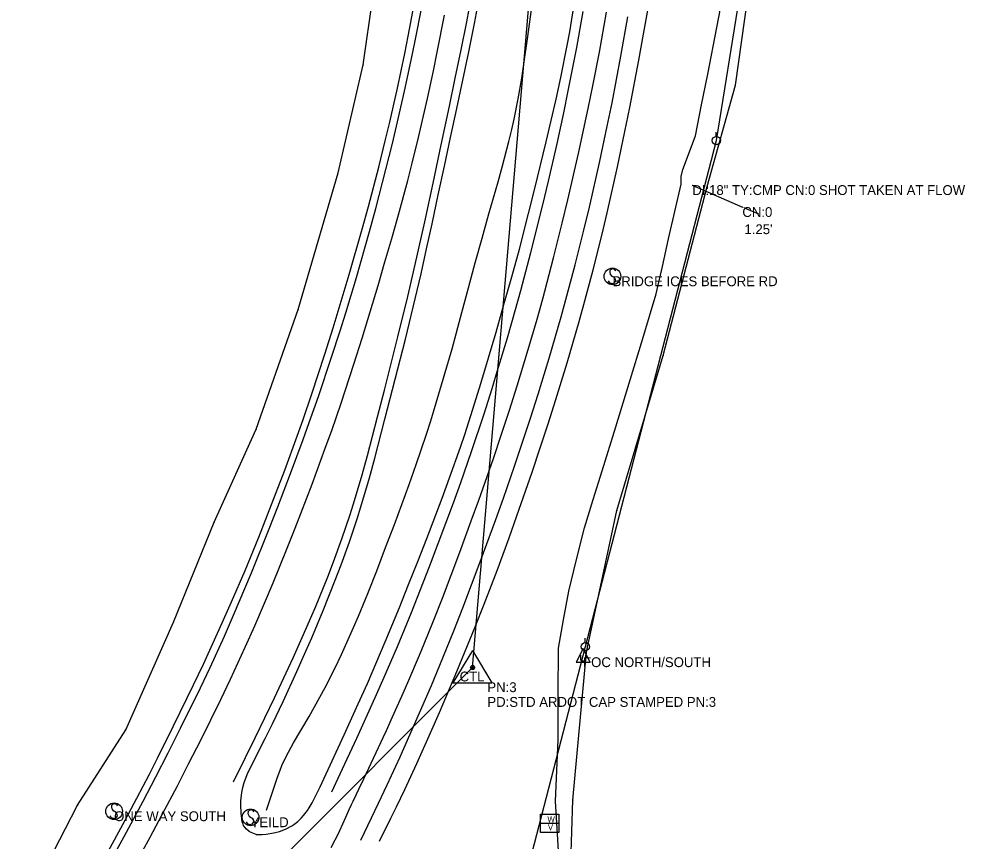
# Model space of a CAD drawing. Extents: x 1676038 to 1677961, y 226475 to 233854.
# Drawn here: x 1677137.5 to 1677618.5, y 228300.9 to 228719 of the extents above; entities that cross this region are included whole.
import ezdxf

# ---------------------------------------------------------------- set-up
doc = ezdxf.new("R2010")
doc.units = 0
for name, color, linetype in [('S_BASELINE', 7, 'Continuous'), ('S_CROSS_DRAIN', 7, 'Continuous'), ('S_CROSS_DRAIN_ANNOT', 7, 'Continuous'), ('S_DITCHLINE', 7, 'Continuous'), ('S_DRG_PT_SYM', 7, 'Continuous'), ('S_DROP_INLET_ANNOT', 7, 'Continuous'), ('S_EDGE_PAVEMENT', 7, 'Continuous'), ('S_ELECTRIC_UTILITIES', 7, 'Continuous'), ('S_FIBER_OPTIC_CABLE', 7, 'Continuous'), ('S_MSC_PT_SYM', 7, 'Continuous'), ('S_PAVEMENT_CROWN', 7, 'Continuous'), ('S_PRIMARY_CTL', 7, 'Continuous'), ('S_PRIMARY_CTL_ANNOT', 7, 'Continuous'), ('S_SHOULDER', 7, 'Continuous'), ('S_SIGN', 7, 'Continuous'), ('S_SIGN_ANNOT', 7, 'Continuous'), ('S_UNDERGROUND_CABLE', 7, 'Continuous'), ('S_UTILITY_POLE', 7, 'Continuous'), ('S_UTILITY_POLE_ANNOT', 7, 'Continuous'), ('S_UTL_PT_SYM', 7, 'Continuous'), ('S_WATER_UTILITIES', 7, 'Continuous')]:
    doc.layers.add(name, color=color, linetype=linetype)

msp = doc.modelspace()

# ---------------------------------------------------------------- linework, layer by layer
at = {"layer": 'S_BASELINE'}
for p, q in [((1677368.16, 228389.18), (1677436.38, 229190.98)), ((1676625.89, 227646.73), (1677368.16, 228389.18))]:
    msp.add_line(p, q, dxfattribs=at)
at = {"layer": 'S_CROSS_DRAIN'}
msp.add_line((1677479.85, 228634.45), (1677505.31, 228623.28), dxfattribs=at)
at = {"layer": 'S_DITCHLINE'}
for points in [[(1677412.08, 228293.34), (1677411.18, 228307.32), (1677410.29, 228321.3), (1677410.97, 228336.87), (1677411.65, 228352.45), (1677411.72, 228375.7), (1677411.79, 228398.95), (1677414.39, 228413.46), (1677417, 228427.97), (1677421, 228444.05), (1677425, 228460.14), (1677429.48, 228474.66), (1677433.97, 228489.17), (1677440.9, 228511.49), (1677447.83, 228533.8), (1677454.65, 228556.51), (1677461.47, 228579.22), (1677464.64, 228593.16), (1677467.81, 228607.09), (1677470.98, 228621.03), (1677474.15, 228634.96), (1677474.23, 228638.85), (1677475, 228642.39), (1677481.44, 228659.54), (1677484.58, 228675.24), (1677487.72, 228690.94), (1677492.32, 228714.69), (1677496.91, 228738.44)], [(1677263.31, 228316.69), (1677268.91, 228333.35), (1677270.24, 228336.98), (1677271.23, 228339.35), (1677273.42, 228344.01), (1677277.08, 228350.84), (1677285, 228364.25), (1677287.81, 228369.15), (1677293.18, 228379.05), (1677298.24, 228389.08), (1677301.46, 228395.84), (1677307.62, 228409.48), (1677310.09, 228415.23), (1677314.88, 228426.78), (1677319.5, 228438.42), (1677323.95, 228450.13), (1677328.39, 228461.83), (1677335.84, 228482.23), (1677339.45, 228492.47), (1677344.65, 228507.89), (1677346.85, 228514.69), (1677351.07, 228528.35), (1677355.11, 228542.07), (1677357.71, 228551.25), (1677362.74, 228569.64), (1677366.12, 228582.28), (1677369.49, 228594.93), (1677372.96, 228607.55), (1677376.46, 228619.79), (1677381.16, 228636.11), (1677383.43, 228644.29), (1677386.61, 228656.6), (1677388.07, 228662.79), (1677389.21, 228667.99), (1677391.28, 228678.43), (1677393.11, 228688.92), (1677394.24, 228695.93), (1677396.31, 228709.99), (1677399.2, 228731.39)], [(1677513.71, 228619.62), (1677506.9, 228622.64)]]:
    msp.add_lwpolyline(points, dxfattribs=at)
at = {"layer": 'S_DRG_PT_SYM'}
for points in [[(1677479.85, 228634.45), (1677479.85, 228634.5), (1677479.85, 228634.45), (1677479.8, 228634.45), (1677479.85, 228634.45), (1677479.85, 228634.4), (1677479.85, 228634.45), (1677479.9, 228634.45)], [(1677505.31, 228623.28), (1677505.31, 228623.33), (1677505.31, 228623.28), (1677505.26, 228623.28), (1677505.31, 228623.28), (1677505.31, 228623.23), (1677505.31, 228623.28), (1677505.36, 228623.28)], [(1677506.24, 228623.01), (1677506.24, 228623.06), (1677506.24, 228623.01), (1677506.19, 228623.01), (1677506.24, 228623.01), (1677506.24, 228622.96), (1677506.24, 228623.01), (1677506.29, 228623.01)]]:
    msp.add_lwpolyline(points, dxfattribs=at)
at = {"layer": 'S_EDGE_PAVEMENT'}
for points in [[(1677246.51, 228331.03), (1677252.72, 228343.36), (1677257.69, 228353.46), (1677267.42, 228373.76), (1677276.91, 228394.14), (1677281.53, 228404.38), (1677288.22, 228419.85), (1677294.48, 228435.24), (1677297.46, 228442.99), (1677301.73, 228454.69), (1677305.72, 228466.49), (1677307.61, 228472.42), (1677311.95, 228487.11), (1677314.65, 228496.96), (1677319.82, 228516.72), (1677323.3, 228530.28), (1677326.77, 228543.84), (1677330.18, 228557.41), (1677335.16, 228577.8), (1677338.13, 228590.46), (1677340.98, 228603.14), (1677343.84, 228615.83), (1677348.08, 228635.39), (1677352.22, 228654.98), (1677356.37, 228674.57), (1677359.37, 228688.89), (1677362.37, 228703.21), (1677365.25, 228717.56), (1677368.85, 228736.91)], [(1677186.05, 228294.21), (1677190.97, 228303.18), (1677200.63, 228321.22), (1677207.04, 228333.55), (1677213.45, 228345.88), (1677219.73, 228358.28), (1677229.84, 228378.83), (1677234.74, 228389.18), (1677241.98, 228405.14), (1677246.65, 228415.85), (1677255.71, 228437.39), (1677264.73, 228459.73), (1677269.13, 228470.95), (1677275.59, 228487.82), (1677282.01, 228505.16), (1677285.14, 228513.85), (1677289.74, 228526.93), (1677296.49, 228547.02), (1677300.82, 228560.46), (1677303.63, 228569.45), (1677309.08, 228587.48), (1677315.76, 228610.85), (1677318.95, 228622.58), (1677324.09, 228642.38), (1677327.35, 228655.61), (1677329.47, 228664.46), (1677333.53, 228682.18), (1677337.48, 228700.38), (1677339.36, 228709.5), (1677342.05, 228723.2)], [(1677296.58, 228326.01), (1677300.87, 228335.06), (1677309.32, 228353.24), (1677318.65, 228373.88), (1677323.21, 228384.25), (1677329.89, 228399.87), (1677337.04, 228417.24), (1677341.68, 228428.87), (1677346.19, 228440.55), (1677350.69, 228452.24), (1677358.39, 228472.95), (1677362.14, 228483.34), (1677367.59, 228498.98), (1677373.97, 228518.18), (1677378.05, 228531.03), (1677380.69, 228539.62), (1677385.82, 228556.85), (1677389.94, 228571.29), (1677392.6, 228580.94), (1677397.76, 228600.29), (1677403.84, 228624.42), (1677406.74, 228636.52), (1677410.91, 228654.71), (1677414.49, 228671.28), (1677416.78, 228682.34), (1677421.11, 228704.51), (1677424.43, 228722.78)], [(1677311.4, 228301.34), (1677320.34, 228320.14), (1677324.74, 228329.57), (1677331.25, 228343.78), (1677338.18, 228359.24), (1677347.19, 228379.97), (1677351.56, 228390.39), (1677358.61, 228407.82), (1677363.18, 228419.49), (1677367.62, 228431.2), (1677372.06, 228442.92), (1677379.97, 228464.52), (1677383.84, 228475.35), (1677389.5, 228491.64), (1677393.54, 228503.78), (1677397.58, 228515.92), (1677401.47, 228528.12), (1677407.09, 228546.47), (1677413.2, 228567.53), (1677416.13, 228578.1), (1677420.36, 228594), (1677424.77, 228611.51), (1677427.58, 228623.22), (1677432.9, 228646.7), (1677436.65, 228664.42), (1677439.04, 228676.26), (1677443.55, 228699.98), (1677447.09, 228720.05)]]:
    msp.add_lwpolyline(points, dxfattribs=at)
at = {"layer": 'S_ELECTRIC_UTILITIES'}
for p, q in [((1677492.08, 228657.14), (1677537.01, 228935.14)), ((1677425.49, 228399.8), (1677492.08, 228657.14)), ((1677343.16, 228080.48), (1677425.49, 228399.8))]:
    msp.add_line(p, q, dxfattribs=at)
at = {"layer": 'S_FIBER_OPTIC_CABLE'}
for p, q in [((1677312.48, 228695.6), (1677320.94, 228755.15)), ((1677501.74, 228685.3), (1677511.42, 228753.9)), ((1677299.85, 228640.69), (1677312.48, 228695.6)), ((1677487.34, 228633.72), (1677501.74, 228685.3)), ((1677279.39, 228571.17), (1677299.85, 228640.69)), ((1677465.1, 228547.8), (1677487.34, 228633.72)), ((1677258.19, 228510.33), (1677279.39, 228571.17)), ((1677441.54, 228468.97), (1677465.1, 228547.8)), ((1677236.83, 228463.03), (1677258.19, 228510.33)), ((1677425.99, 228396.98), (1677441.54, 228468.97)), ((1677216.05, 228412.32), (1677236.83, 228463.03)), ((1677191.77, 228357.44), (1677216.05, 228412.32)), ((1677419.05, 228321.79), (1677425.99, 228396.98)), ((1677167.35, 228319.14), (1677191.77, 228357.44)), ((1677150.44, 228286.49), (1677167.35, 228319.14)), ((1677416.97, 228249.14), (1677419.05, 228321.79))]:
    msp.add_line(p, q, dxfattribs=at)
at = {"layer": 'S_MSC_PT_SYM'}
msp.add_lwpolyline([(1677506.24, 228623.01), (1677506.24, 228623.06), (1677506.24, 228623.01), (1677506.19, 228623.01), (1677506.24, 228623.01), (1677506.24, 228622.96), (1677506.24, 228623.01), (1677506.29, 228623.01)], dxfattribs=at)
at = {"layer": 'S_PAVEMENT_CROWN'}
for points in [[(1677196.51, 228288.75), (1677204.2, 228302.85), (1677211.76, 228317.01), (1677217.9, 228328.74), (1677223.93, 228340.53), (1677229.95, 228352.32), (1677240.15, 228372.88), (1677245.11, 228383.23), (1677252.58, 228399.47), (1677257.41, 228410.37), (1677266.74, 228432.31), (1677273.54, 228448.96), (1677277.95, 228460.1), (1677286.55, 228482.48), (1677293.27, 228500.66), (1677296.53, 228509.78), (1677301.29, 228523.52), (1677307.81, 228543.39), (1677311.99, 228556.69), (1677316.04, 228570.04), (1677320.08, 228583.38), (1677323.61, 228595.39), (1677327.13, 228607.39), (1677330.53, 228619.43), (1677335.2, 228636.87), (1677337.44, 228645.62), (1677340.66, 228658.77), (1677345.2, 228678.58), (1677348.21, 228692.64), (1677350.13, 228702.03), (1677353.81, 228720.85)], [(1677296.33, 228297.69), (1677298.28, 228301.57), (1677299.22, 228303.5), (1677300.6, 228306.39), (1677303.67, 228313.1), (1677305.44, 228316.94), (1677306.63, 228319.53), (1677307.44, 228321.25), (1677309.06, 228324.72), (1677310.3, 228327.34), (1677312.78, 228332.59), (1677320.28, 228348.45), (1677322.71, 228353.67), (1677324.32, 228357.15), (1677327.49, 228364.11), (1677332.15, 228374.55), (1677335.2, 228381.52), (1677341.15, 228395.52), (1677343.53, 228401.28), (1677348.21, 228412.85), (1677352.78, 228424.47), (1677357.22, 228436.16), (1677361.66, 228447.85), (1677367.48, 228463.7), (1677371.28, 228474.3), (1677378.7, 228495.54), (1677382.79, 228507.79), (1677386.88, 228520.03), (1677390.81, 228532.33), (1677396.47, 228550.86), (1677400.94, 228566.35), (1677403.8, 228576.72), (1677409.3, 228597.51), (1677413.73, 228615.14), (1677416.58, 228626.91), (1677422.04, 228650.52), (1677426.99, 228673.43), (1677429.34, 228684.91), (1677432.69, 228702.16), (1677436.31, 228722.44)]]:
    msp.add_lwpolyline(points, dxfattribs=at)
at = {"layer": 'S_PRIMARY_CTL'}
for p, q in [((1677368.16, 228397.88), (1677358.13, 228381.37)), ((1677368.16, 228397.88), (1677377.98, 228381.37)), ((1677358.13, 228381.37), (1677377.98, 228381.37))]:
    msp.add_line(p, q, dxfattribs=at)
for radius in [1.04, 0.609, 0.344]:
    msp.add_circle((1677368.16, 228389.18), radius, dxfattribs=at)
at = {"layer": 'S_SHOULDER'}
for points in [[(1677258.04, 228304.22), (1677255.6, 228305.24), (1677254.55, 228305.85), (1677253.21, 228306.92), (1677252.15, 228308.18), (1677251.74, 228308.88), (1677251.47, 228309.49), (1677251.06, 228310.8), (1677250.79, 228312.2), (1677250.52, 228315.11), (1677250.34, 228319.29), (1677250.36, 228321.33), (1677250.6, 228324.34), (1677250.8, 228325.61), (1677251.36, 228328.15), (1677252.1, 228330.67), (1677253.95, 228335.71), (1677254.15, 228336.21), (1677255.21, 228338.26), (1677262.73, 228353.12), (1677266.4, 228360.58), (1677271.8, 228371.84), (1677278.85, 228387.15), (1677283.4, 228397.43), (1677286.37, 228404.31), (1677292.16, 228418.14), (1677298.33, 228433.58), (1677301.29, 228441.35), (1677305.53, 228453.06), (1677309.51, 228464.87), (1677311.38, 228470.81), (1677315.7, 228485.63), (1677318.39, 228495.57), (1677323.56, 228515.5), (1677328.81, 228535.84), (1677334.05, 228556.18), (1677339.03, 228576.58), (1677341.95, 228589.32), (1677344.74, 228602.09), (1677347.53, 228614.87), (1677350.68, 228629.49), (1677353.83, 228644.12), (1677356.97, 228658.75), (1677360.12, 228673.38), (1677363.17, 228687.78), (1677366.22, 228702.18), (1677369.13, 228716.61), (1677372.74, 228735.88)], [(1677183.02, 228295.95), (1677190.34, 228309.3), (1677197.49, 228322.74), (1677203.83, 228334.93), (1677207.99, 228343.09), (1677216.17, 228359.47), (1677226.3, 228380.39), (1677231.26, 228390.9), (1677240.91, 228411.95), (1677245.61, 228422.54), (1677252.47, 228438.49), (1677259.44, 228455.42), (1677263.95, 228466.77), (1677272.66, 228489.58), (1677278.93, 228506.75), (1677281.97, 228515.37), (1677286.42, 228528.33), (1677293.02, 228548.49), (1677297.26, 228561.99), (1677301.35, 228575.53), (1677305.44, 228589.07), (1677312.09, 228612.07), (1677315.28, 228623.6), (1677320.48, 228643.58), (1677323.76, 228656.95), (1677325.86, 228665.88), (1677329.89, 228683.79), (1677333.64, 228701.43), (1677335.43, 228710.27), (1677338, 228723.56)], [(1677258.07, 228304.25), (1677261.15, 228304.28), (1677263.17, 228304.45), (1677267.15, 228305.12), (1677269.94, 228305.86), (1677271.32, 228306.32), (1677273.33, 228307.14), (1677276.2, 228308.66), (1677277.25, 228309.35), (1677279.22, 228310.9), (1677281.05, 228312.64), (1677282.18, 228313.88), (1677284.24, 228316.54), (1677285.09, 228317.8), (1677286.63, 228320.4), (1677288.02, 228323.09), (1677290.58, 228328.58), (1677296.73, 228341.79), (1677302.89, 228355.01), (1677310.02, 228370.65), (1677314.66, 228381.14), (1677323.69, 228402.22), (1677330.92, 228419.68), (1677335.64, 228431.36), (1677340.25, 228443.08), (1677344.87, 228454.8), (1677352.7, 228475.34), (1677356.49, 228485.66), (1677361.96, 228501.22), (1677364.13, 228507.66), (1677368.32, 228520.6), (1677372.34, 228533.59), (1677376.2, 228546.63), (1677380.07, 228559.67), (1677384.08, 228573.72), (1677388.09, 228587.76), (1677391.94, 228601.85), (1677396.65, 228619.99), (1677399.68, 228632.11), (1677405.55, 228656.41), (1677410.62, 228678.2), (1677413.01, 228689.12), (1677416.3, 228705.55), (1677417.54, 228712.44), (1677419.8, 228726.27)], [(1677320.78, 228300.93), (1677326.57, 228312.56), (1677329.42, 228318.39), (1677333.63, 228327.18), (1677339.81, 228340.42), (1677346.78, 228355.89), (1677351.32, 228366.26), (1677360.15, 228387.11), (1677369.47, 228409.91), (1677374, 228421.35), (1677380.61, 228438.59), (1677386.72, 228455.17), (1677390.68, 228466.26), (1677398.39, 228488.52), (1677402.48, 228500.84), (1677406.57, 228513.16), (1677410.53, 228525.53), (1677416.26, 228544.14), (1677422.36, 228565.08), (1677425.27, 228575.6), (1677429.45, 228591.41), (1677433.78, 228608.79), (1677436.54, 228620.41), (1677441.77, 228643.7), (1677445.59, 228661.79), (1677448.04, 228673.87), (1677452.69, 228698.07), (1677455.02, 228711.19), (1677457.35, 228724.31)]]:
    msp.add_lwpolyline(points, dxfattribs=at)
at = {"layer": 'S_SIGN'}
for centre in [(1677439.27, 228588.08), (1677185.9, 228316.07), (1677255.3, 228313)]:
    msp.add_circle(centre, 4.24, dxfattribs=at)
for centre, radius, start, end in [((1677440.44, 228590.33), 2.55, 167.1196, 241.9813), ((1677439.4, 228590.23), 1.62, 16.5258, 156.8957), ((1677439.01, 228586.68), 2.17, 204.641, 335.359), ((1677438.57, 228585.8), 2.38, 358.6529, 73.7063), ((1677186.03, 228318.23), 1.62, 16.5258, 156.8957), ((1677187.07, 228318.33), 2.55, 167.1196, 241.9813), ((1677185.2, 228313.79), 2.38, 358.6529, 73.7063), ((1677256.46, 228315.26), 2.55, 167.1196, 241.9813), ((1677255.42, 228315.16), 1.62, 16.5258, 156.8957), ((1677185.64, 228314.67), 2.17, 204.641, 335.359), ((1677255.03, 228311.6), 2.17, 204.641, 335.359), ((1677254.59, 228310.72), 2.38, 358.6529, 73.7063)]:
    msp.add_arc(centre, radius, start, end, dxfattribs=at)
at = {"layer": 'S_UNDERGROUND_CABLE'}
for p, q in [((1677424.33, 228398.92), (1677420.8, 228391.83)), ((1677424.33, 228398.92), (1677427.81, 228391.83)), ((1677420.8, 228391.83), (1677427.81, 228391.83)), ((1677423.13, 228393.07), (1677423.13, 228395.51)), ((1677423.75, 228392.41), (1677423.13, 228393.07)), ((1677424.95, 228392.41), (1677423.75, 228392.41)), ((1677425.49, 228393.07), (1677424.95, 228392.41)), ((1677425.49, 228395.51), (1677425.49, 228393.07))]:
    msp.add_line(p, q, dxfattribs=at)
at = {"layer": 'S_UTILITY_POLE'}
for p, q in [((1677491.96, 228659.28), (1677491.96, 228661.39)), ((1677425.36, 228401.94), (1677425.36, 228404.05))]:
    msp.add_line(p, q, dxfattribs=at)
for centre in [(1677492.08, 228657.14), (1677425.49, 228399.8)]:
    msp.add_circle(centre, 2.13, dxfattribs=at)
at = {"layer": 'S_UTL_PT_SYM'}
for points in [[(1677312.48, 228695.6), (1677312.48, 228695.65), (1677312.48, 228695.6), (1677312.43, 228695.6), (1677312.48, 228695.6), (1677312.48, 228695.55), (1677312.48, 228695.6), (1677312.53, 228695.6)], [(1677501.74, 228685.3), (1677501.74, 228685.35), (1677501.74, 228685.3), (1677501.69, 228685.3), (1677501.74, 228685.3), (1677501.74, 228685.25), (1677501.74, 228685.3), (1677501.79, 228685.3)], [(1677492.08, 228657.14), (1677492.08, 228657.19), (1677492.08, 228657.14), (1677492.03, 228657.14), (1677492.08, 228657.14), (1677492.08, 228657.09), (1677492.08, 228657.14), (1677492.13, 228657.14)], [(1677299.85, 228640.69), (1677299.85, 228640.74), (1677299.85, 228640.69), (1677299.8, 228640.69), (1677299.85, 228640.69), (1677299.85, 228640.64), (1677299.85, 228640.69), (1677299.9, 228640.69)], [(1677487.34, 228633.72), (1677487.34, 228633.77), (1677487.34, 228633.72), (1677487.29, 228633.72), (1677487.34, 228633.72), (1677487.34, 228633.67), (1677487.34, 228633.72), (1677487.39, 228633.72)], [(1677279.39, 228571.17), (1677279.39, 228571.22), (1677279.39, 228571.17), (1677279.34, 228571.17), (1677279.39, 228571.17), (1677279.39, 228571.12), (1677279.39, 228571.17), (1677279.44, 228571.17)], [(1677465.1, 228547.8), (1677465.1, 228547.85), (1677465.1, 228547.8), (1677465.05, 228547.8), (1677465.1, 228547.8), (1677465.1, 228547.75), (1677465.1, 228547.8), (1677465.16, 228547.8)], [(1677258.19, 228510.33), (1677258.19, 228510.38), (1677258.19, 228510.33), (1677258.14, 228510.33), (1677258.19, 228510.33), (1677258.19, 228510.28), (1677258.19, 228510.33), (1677258.24, 228510.33)], [(1677441.54, 228468.97), (1677441.54, 228469.02), (1677441.54, 228468.97), (1677441.49, 228468.97), (1677441.54, 228468.97), (1677441.54, 228468.92), (1677441.54, 228468.97), (1677441.59, 228468.97)], [(1677236.83, 228463.03), (1677236.83, 228463.08), (1677236.83, 228463.03), (1677236.78, 228463.03), (1677236.83, 228463.03), (1677236.83, 228462.98), (1677236.83, 228463.03), (1677236.88, 228463.03)], [(1677216.05, 228412.32), (1677216.05, 228412.37), (1677216.05, 228412.32), (1677216, 228412.32), (1677216.05, 228412.32), (1677216.05, 228412.27), (1677216.05, 228412.32), (1677216.1, 228412.32)], [(1677425.49, 228399.8), (1677425.49, 228399.85), (1677425.49, 228399.8), (1677425.44, 228399.8), (1677425.49, 228399.8), (1677425.49, 228399.75), (1677425.49, 228399.8), (1677425.54, 228399.8)], [(1677425.99, 228396.98), (1677425.99, 228397.03), (1677425.99, 228396.98), (1677425.94, 228396.98), (1677425.99, 228396.98), (1677425.99, 228396.93), (1677425.99, 228396.98), (1677426.04, 228396.98)], [(1677191.77, 228357.44), (1677191.77, 228357.49), (1677191.77, 228357.44), (1677191.72, 228357.44), (1677191.77, 228357.44), (1677191.77, 228357.39), (1677191.77, 228357.44), (1677191.82, 228357.44)], [(1677167.35, 228319.14), (1677167.35, 228319.19), (1677167.35, 228319.14), (1677167.3, 228319.14), (1677167.35, 228319.14), (1677167.35, 228319.09), (1677167.35, 228319.14), (1677167.4, 228319.14)], [(1677419.05, 228321.79), (1677419.05, 228321.84), (1677419.05, 228321.79), (1677419, 228321.79), (1677419.05, 228321.79), (1677419.05, 228321.74), (1677419.05, 228321.79), (1677419.1, 228321.79)]]:
    msp.add_lwpolyline(points, dxfattribs=at)
at = {"layer": 'S_WATER_UTILITIES'}
for p, q in [((1677402.64, 228314.69), (1677412.06, 228314.69)), ((1677402.64, 228305.27), (1677402.64, 228314.69)), ((1677412.06, 228314.69), (1677412.06, 228305.27)), ((1677402.64, 228310), (1677412.06, 228310)), ((1677412.06, 228305.27), (1677402.64, 228305.27))]:
    msp.add_line(p, q, dxfattribs=at)

# ---------------------------------------------------------------- texts
at = {"layer": 'S_CROSS_DRAIN_ANNOT'}
for s, p in [('DI:18" TY:CMP CN:0 SHOT TAKEN AT FLOW', (1677479.85, 228629.45)), ('CN:0', (1677505.31, 228618.28))]:
    msp.add_text(s, height=5, dxfattribs=at).set_placement(p)
at = {"layer": 'S_DROP_INLET_ANNOT'}
msp.add_text("1.25'", height=5, dxfattribs=at).set_placement((1677506.38, 228609.54))
at = {"layer": 'S_PRIMARY_CTL'}
msp.add_text('CTL', height=5, rotation=360, dxfattribs=at).set_placement((1677361.57, 228382.11))
at = {"layer": 'S_PRIMARY_CTL_ANNOT'}
for s, p in [('PN:3', (1677375.66, 228376.68)), ('PD:STD ARDOT CAP STAMPED PN:3', (1677375.66, 228369.18))]:
    msp.add_text(s, height=5, dxfattribs=at).set_placement(p)
at = {"layer": 'S_SIGN_ANNOT'}
for s, p in [('BRIDGE ICES BEFORE RD', (1677439.27, 228583.08)), ('ONE WAY SOUTH', (1677185.9, 228311.07)), ('YEILD', (1677255.3, 228308))]:
    msp.add_text(s, height=5, dxfattribs=at).set_placement(p)
at = {"layer": 'S_UTILITY_POLE_ANNOT'}
msp.add_text('FOC NORTH/SOUTH', height=5, dxfattribs=at).set_placement((1677424.33, 228389.39))
at = {"layer": 'S_WATER_UTILITIES'}
for s, p in [('W', (1677406.19, 228310.53)), ('V', (1677406.43, 228306.47))]:
    msp.add_text(s, height=3, rotation=360, dxfattribs=at).set_placement(p)

doc.saveas('drawing.dxf')
